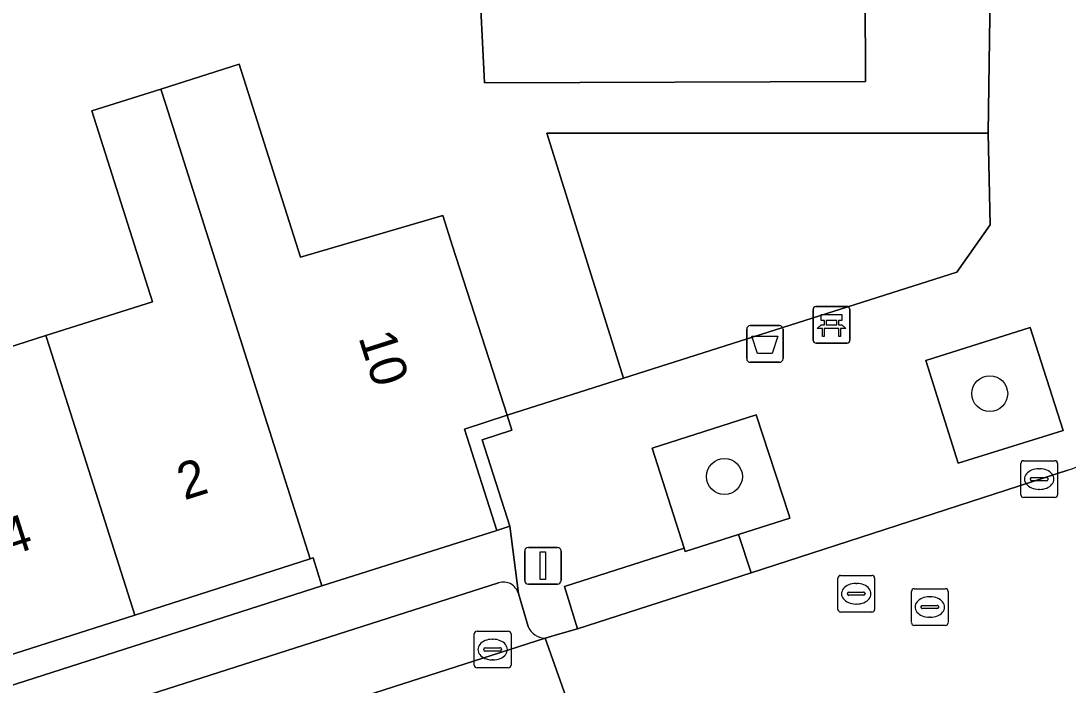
# Model space of a CAD drawing. Extents: x 159716 to 160783, y 383290 to 384031.
# Drawn here: x 160111.85 to 160140.37, y 383683.23 to 383701.33 of the extents above; entities that cross this region are included whole.
import ezdxf

# ---------------------------------------------------------------- set-up
doc = ezdxf.new("R2010")
doc.units = 0
for name, color, linetype in [('IMGEO_Afvalbak', 7, 'Continuous'), ('IMGEO_Bank', 7, 'Continuous'), ('IMGEO_Boom', 7, 'Continuous'), ('IMGEO_Erf', 7, 'Continuous'), ('IMGEO_Groenvoorziening', 7, 'Continuous'), ('IMGEO_Kolk', 7, 'Continuous'), ('IMGEO_Lichtmast', 7, 'Continuous'), ('IMGEO_Pand', 7, 'Continuous'), ('IMGEO_Pand_nummerreeks', 7, 'Continuous'), ('IMGEO_Parkeervlak_open', 7, 'Continuous'), ('IMGEO_Rijbaan_lokaal_open', 7, 'Continuous'), ('IMGEO_Rioolput', 7, 'Continuous'), ('IMGEO_Voetpad_open', 7, 'Continuous')]:
    doc.layers.add(name, color=color, linetype=linetype)

msp = doc.modelspace()

# ---------------------------------------------------------------- linework, layer by layer
at = {"layer": 'IMGEO_Afvalbak'}
for p, q in [((160131.716, 383693.027), (160132.506, 383693.027)), ((160132.506, 383693.027), (160131.716, 383693.027)), ((160131.616, 383692.127), (160131.616, 383692.927)), ((160131.616, 383692.927), (160131.616, 383692.127)), ((160132.606, 383692.927), (160132.606, 383692.127)), ((160132.606, 383692.127), (160132.606, 383692.927)), ((160132.506, 383692.027), (160131.716, 383692.027)), ((160131.716, 383692.027), (160132.506, 383692.027))]:
    msp.add_line(p, q, dxfattribs=at)
msp.add_lwpolyline([(160131.759, 383692.741), (160132.463, 383692.741), (160132.314, 383692.271), (160131.908, 383692.271), (160131.759, 383692.741)], dxfattribs=at)
for centre, start, end in [((160131.716, 383692.927), 90, 180), ((160131.716, 383692.927), 90, 180), ((160132.506, 383692.927), 0, 90), ((160132.506, 383692.927), 360, 90), ((160131.716, 383692.127), 180, 270), ((160131.716, 383692.127), 180, 270), ((160132.506, 383692.127), 270, 0), ((160132.506, 383692.127), 270, 0)]:
    msp.add_arc(centre, 0.1, start, end, dxfattribs=at)
at = {"layer": 'IMGEO_Bank'}
for p, q in [((160133.502, 383693.55), (160134.343, 383693.55)), ((160134.343, 383693.55), (160133.502, 383693.55)), ((160133.427, 383692.625), (160133.427, 383693.466)), ((160133.427, 383693.466), (160133.427, 383692.625)), ((160134.427, 383693.475), (160134.427, 383692.634)), ((160134.427, 383692.634), (160134.427, 383693.475)), ((160134.124, 383692.948), (160133.731, 383692.948)), ((160133.736, 383693.056), (160133.736, 383693.162)), ((160133.78, 383693.162), (160133.78, 383693.056)), ((160134.068, 383693.168), (160133.786, 383693.168)), ((160133.786, 383693.05), (160134.068, 383693.05)), ((160134.074, 383693.056), (160134.074, 383693.162)), ((160134.118, 383693.162), (160134.118, 383693.056)), ((160134.352, 383692.55), (160133.511, 383692.55)), ((160133.511, 383692.55), (160134.352, 383692.55))]:
    msp.add_line(p, q, dxfattribs=at)
for points in [[(160133.73, 383693.168), (160133.644, 383693.168), (160133.644, 383693.329), (160134.207, 383693.329), (160134.207, 383693.168), (160134.124, 383693.168)], [(160133.674, 383692.948), (160133.532, 383692.948), (160133.644, 383693.05), (160133.73, 383693.05)], [(160134.124, 383693.05), (160134.207, 383693.05), (160134.319, 383692.948), (160134.18, 383692.948)], [(160133.724, 383692.941), (160133.724, 383692.734), (160133.681, 383692.734), (160133.681, 383692.941)], [(160134.174, 383692.941), (160134.174, 383692.734), (160134.13, 383692.734), (160134.13, 383692.941)]]:
    msp.add_lwpolyline(points, dxfattribs=at)
for centre, radius, start, end in [((160133.505, 383693.472), 0.0779, 92.4484, 184.2845), ((160133.505, 383693.472), 0.0779, 92.4484, 184.2845), ((160134.349, 383693.472), 0.0779, 2.4484, 94.2845), ((160134.349, 383693.472), 0.0779, 2.4484, 94.2845), ((160133.674, 383692.941), 0.00671, 2.8957, 87.1043), ((160133.731, 383692.941), 0.00671, 92.8957, 177.1043), ((160133.729, 383693.161), 0.00671, 2.8957, 87.1043), ((160133.729, 383693.057), 0.00671, 272.8957, 357.1043), ((160133.786, 383693.161), 0.00671, 92.8957, 177.1043), ((160133.786, 383693.057), 0.00671, 182.8957, 267.1043), ((160134.068, 383693.161), 0.00671, 2.8957, 87.1043), ((160134.068, 383693.057), 0.00671, 272.8957, 357.1043), ((160134.125, 383693.161), 0.00671, 92.8957, 177.1043), ((160134.125, 383693.057), 0.00671, 182.8957, 267.1043), ((160134.123, 383692.941), 0.00671, 2.8957, 87.1043), ((160134.18, 383692.941), 0.00671, 92.8957, 177.1043), ((160133.505, 383692.628), 0.0779, 182.4484, 274.2845), ((160133.505, 383692.628), 0.0779, 182.4484, 274.2845), ((160134.349, 383692.628), 0.0779, 272.4484, 4.2845), ((160134.349, 383692.628), 0.0779, 272.4484, 4.2845)]:
    msp.add_arc(centre, radius, start, end, dxfattribs=at)
at = {"layer": 'IMGEO_Boom'}
for centre in [(160138.235, 383691.174), (160131.01, 383688.915)]:
    msp.add_circle(centre, 0.489, dxfattribs=at)
at = {"layer": 'IMGEO_Erf'}
for points in [[(160109.585, 383691.818), (160112.53, 383692.755), (160115.435, 383693.679), (160113.782, 383698.877), (160115.661, 383699.474), (160117.796, 383700.153), (160119.467, 383694.897), (160123.342, 383696.024), (160123.608, 383695.196), (160125.089, 383690.591), (160128.261, 383691.6), (160126.173, 383698.271), (160138.197, 383698.271), (160138.247, 383702.107)], [(160134.846, 383702.081), (160134.849, 383699.683), (160124.473, 383699.641), (160124.351, 383702.208)]]:
    msp.add_lwpolyline(points, dxfattribs=at)
for points in [[(160125.089, 383690.591), (160123.935, 383690.21), (160124.812, 383687.446), (160125.17, 383687.56), (160124.416, 383689.912), (160125.22, 383690.183)], [(160120.049, 383685.937), (160119.807, 383686.699), (160119.731, 383686.675), (160114.952, 383685.141), (160110.171, 383683.607), (160105.39, 383682.072), (160100.609, 383680.538), (160100.221, 383680.413), (160100.464, 383679.651)]]:
    msp.add_lwpolyline(points, close=True, dxfattribs=at)
at = {"layer": 'IMGEO_Groenvoorziening'}
for points in [[(160138.246, 383695.773), (160138.197, 383698.271), (160126.173, 383698.271), (160128.261, 383691.6), (160137.338, 383694.486)], [(160140.234, 383690.171), (160139.335, 383692.979), (160136.497, 383692.079), (160137.376, 383689.279)], [(160129.914, 383686.967), (160129.944, 383686.873), (160131.397, 383687.337), (160132.794, 383687.784), (160132.762, 383687.881), (160131.876, 383690.592), (160129.042, 383689.685)]]:
    msp.add_lwpolyline(points, close=True, dxfattribs=at)
at = {"layer": 'IMGEO_Kolk'}
for p, q in [((160139.082, 383688.419), (160139.082, 383689.271)), ((160139.157, 383689.345), (160140.009, 383689.345)), ((160140.083, 383689.271), (160140.083, 383688.419)), ((160139.57, 383689.125), (160139.595, 383689.125)), ((160139.341, 383688.839), (160139.341, 383688.851)), ((160139.779, 383688.802), (160139.381, 383688.802)), ((160139.384, 383688.888), (160139.782, 383688.888)), ((160139.825, 383688.851), (160139.825, 383688.839)), ((160139.593, 383688.565), (160139.568, 383688.565)), ((160140.009, 383688.345), (160139.157, 383688.345)), ((160124.272, 383684.701), (160125.124, 383684.701)), ((160124.197, 383683.775), (160124.197, 383684.627)), ((160124.685, 383684.481), (160124.71, 383684.481)), ((160125.198, 383684.627), (160125.198, 383683.775)), ((160124.456, 383684.195), (160124.456, 383684.207)), ((160124.894, 383684.158), (160124.496, 383684.158)), ((160124.499, 383684.244), (160124.897, 383684.244)), ((160124.94, 383684.207), (160124.94, 383684.195)), ((160124.708, 383683.921), (160124.683, 383683.921)), ((160125.124, 383683.701), (160124.272, 383683.701))]:
    msp.add_line(p, q, dxfattribs=at)
for points in [[(160139.082, 383688.419), (160139.082, 383689.271)], [(160139.157, 383689.345), (160140.009, 383689.345)], [(160140.083, 383689.271), (160140.083, 383688.419)], [(160140.009, 383688.345), (160139.157, 383688.345)], [(160124.272, 383684.701), (160125.124, 383684.701)], [(160124.197, 383683.775), (160124.197, 383684.627)], [(160125.198, 383684.627), (160125.198, 383683.775)], [(160125.124, 383683.701), (160124.272, 383683.701)]]:
    msp.add_lwpolyline(points, dxfattribs=at)
for centre, radius, start, end in [((160139.159, 383689.269), 0.0765, 91.552, 178.448), ((160139.159, 383689.269), 0.0765, 91.552, 178.448), ((160140.007, 383689.269), 0.0765, 1.552, 88.448), ((160140.007, 383689.269), 0.0765, 1.552, 88.448), ((160139.381, 383688.848), 0.0403, 85.8775, 175.7526), ((160139.378, 383688.838), 0.0366, 178.938, 274.7102), ((160139.782, 383688.845), 0.043, 264.8664, 352.4533), ((160139.786, 383688.85), 0.0386, 1.7309, 96.639), ((160139.159, 383688.421), 0.0765, 181.552, 268.448), ((160139.159, 383688.421), 0.0765, 181.552, 268.448), ((160140.007, 383688.421), 0.0765, 271.552, 358.448), ((160140.007, 383688.421), 0.0765, 271.552, 358.448), ((160124.274, 383684.625), 0.0765, 91.552, 178.448), ((160124.274, 383684.625), 0.0765, 91.552, 178.448), ((160125.122, 383684.625), 0.0765, 1.552, 88.448), ((160125.122, 383684.625), 0.0765, 1.552, 88.448), ((160124.496, 383684.204), 0.0403, 85.8775, 175.7526), ((160124.493, 383684.194), 0.0366, 178.938, 274.7102), ((160124.897, 383684.201), 0.043, 264.8664, 352.4533), ((160124.901, 383684.206), 0.0386, 1.7309, 96.639), ((160124.274, 383683.777), 0.0765, 181.552, 268.448), ((160124.274, 383683.777), 0.0765, 181.552, 268.448), ((160125.122, 383683.777), 0.0765, 271.552, 358.448), ((160125.122, 383683.777), 0.0765, 271.552, 358.448)]:
    msp.add_arc(centre, radius, start, end, dxfattribs=at)
for centre, major_axis, ratio, start_param, end_param in [((160139.569, 383688.845), (-0.387, 0.002), 0.722429, 4.712389, 7.853982), ((160139.594, 383688.845), (-0.39, 0.002), 0.717154, 1.570796, 4.712389), ((160124.684, 383684.201), (-0.387, 0.002), 0.722429, 4.712389, 7.853982), ((160124.709, 383684.201), (-0.39, 0.002), 0.717154, 1.570796, 4.712389)]:
    msp.add_ellipse(centre, major_axis=major_axis, ratio=ratio, start_param=start_param, end_param=end_param, dxfattribs=at)
at = {"layer": 'IMGEO_Lichtmast'}
for p, q in [((160125.67, 383686.984), (160126.46, 383686.984)), ((160126.46, 383686.984), (160125.67, 383686.984)), ((160125.57, 383686.084), (160125.57, 383686.884)), ((160125.57, 383686.884), (160125.57, 383686.084)), ((160126.56, 383686.884), (160126.56, 383686.084)), ((160126.56, 383686.084), (160126.56, 383686.884)), ((160126.46, 383685.984), (160125.67, 383685.984)), ((160125.67, 383685.984), (160126.46, 383685.984))]:
    msp.add_line(p, q, dxfattribs=at)
msp.add_lwpolyline([(160125.99, 383686.859), (160126.14, 383686.859), (160126.14, 383686.109), (160125.99, 383686.109), (160125.99, 383686.859)], dxfattribs=at)
for centre, start, end in [((160125.67, 383686.884), 90, 180), ((160125.67, 383686.884), 90, 180), ((160126.46, 383686.884), 0, 90), ((160126.46, 383686.884), 360, 90), ((160125.67, 383686.084), 180, 270), ((160125.67, 383686.084), 180, 270), ((160126.46, 383686.084), 270, 0), ((160126.46, 383686.084), 270, 0)]:
    msp.add_arc(centre, 0.1, start, end, dxfattribs=at)
at = {"layer": 'IMGEO_Pand'}
for points in [[(160138.221, 383705.895), (160129.395, 383705.861), (160129.058, 383705.86), (160129.073, 383702.227), (160124.351, 383702.208), (160124.473, 383699.641), (160134.849, 383699.683), (160134.846, 383702.081), (160138.247, 383702.107)], [(160123.342, 383696.024), (160119.467, 383694.897), (160117.796, 383700.153), (160115.661, 383699.474), (160115.794, 383699.057), (160119.731, 383686.675), (160119.807, 383686.699), (160120.049, 383685.937), (160124.812, 383687.446), (160123.935, 383690.21), (160125.089, 383690.591), (160123.608, 383695.196)], [(160115.794, 383699.057), (160115.661, 383699.474), (160113.782, 383698.877), (160115.435, 383693.679), (160112.53, 383692.755), (160112.627, 383692.45), (160114.952, 383685.141), (160119.731, 383686.675)], [(160112.627, 383692.45), (160112.53, 383692.755), (160109.585, 383691.818), (160108.018, 383696.744), (160106.18, 383696.159), (160106.252, 383695.932), (160110.171, 383683.607), (160114.952, 383685.141)]]:
    msp.add_lwpolyline(points, close=True, dxfattribs=at)
at = {"layer": 'IMGEO_Parkeervlak_open'}
for points in [[(160124.861, 383686.019), (160096.9, 383677.061)], [(160125.665, 383684.829), (160125.399, 383685.725)], [(160096.699, 383675.06), (160126.127, 383684.515)]]:
    msp.add_lwpolyline(points, dxfattribs=at)
for centre, radius, start, end in [((160124.99, 383685.615), 0.424, 15.0268, 107.6628), ((160126.117, 383684.998), 0.483, 200.4424, 271.1533)]:
    msp.add_arc(centre, radius, start, end, dxfattribs=at)
at = {"layer": 'IMGEO_Rijbaan_lokaal_open'}
for points in [[(160140.365, 383689.087), (160131.741, 383686.293), (160127.013, 383684.761), (160126.463, 383684.611), (160126.127, 383684.515), (160127.305, 383681.179), (160127.453, 383681.227), (160128.426, 383680.973)], [(160097.72, 383671.705), (160127.305, 383681.179), (160126.127, 383684.515), (160096.699, 383675.06), (160080.374, 383669.741)]]:
    msp.add_lwpolyline(points, dxfattribs=at)
msp.add_arc((160138.396, 383694.86), 6.1, 288.8278, 310.6866, dxfattribs=at)
at = {"layer": 'IMGEO_Rioolput'}
for p, q in [((160134.099, 383685.295), (160134.099, 383686.147)), ((160134.174, 383686.221), (160135.026, 383686.221)), ((160135.1, 383686.147), (160135.1, 383685.295)), ((160134.587, 383686.001), (160134.612, 383686.001)), ((160136.178, 383685.859), (160137.03, 383685.859)), ((160134.358, 383685.715), (160134.358, 383685.727)), ((160134.796, 383685.678), (160134.398, 383685.678)), ((160134.401, 383685.764), (160134.799, 383685.764)), ((160134.842, 383685.727), (160134.842, 383685.715)), ((160136.103, 383684.933), (160136.103, 383685.785)), ((160136.591, 383685.639), (160136.616, 383685.639)), ((160137.104, 383685.785), (160137.104, 383684.933)), ((160134.61, 383685.441), (160134.585, 383685.441)), ((160136.362, 383685.353), (160136.362, 383685.365)), ((160136.8, 383685.316), (160136.402, 383685.316)), ((160136.405, 383685.402), (160136.803, 383685.402)), ((160136.846, 383685.365), (160136.846, 383685.353)), ((160135.026, 383685.221), (160134.174, 383685.221)), ((160136.614, 383685.079), (160136.589, 383685.079)), ((160137.03, 383684.859), (160136.178, 383684.859))]:
    msp.add_line(p, q, dxfattribs=at)
for points in [[(160134.099, 383685.295), (160134.099, 383686.147)], [(160134.174, 383686.221), (160135.026, 383686.221)], [(160135.1, 383686.147), (160135.1, 383685.295)], [(160136.178, 383685.859), (160137.03, 383685.859)], [(160136.103, 383684.933), (160136.103, 383685.785)], [(160137.104, 383685.785), (160137.104, 383684.933)], [(160135.026, 383685.221), (160134.174, 383685.221)], [(160137.03, 383684.859), (160136.178, 383684.859)]]:
    msp.add_lwpolyline(points, dxfattribs=at)
for centre, radius, start, end in [((160134.176, 383686.145), 0.0765, 91.552, 178.448), ((160134.176, 383686.145), 0.0765, 91.552, 178.448), ((160135.024, 383686.145), 0.0765, 1.552, 88.448), ((160135.024, 383686.145), 0.0765, 1.552, 88.448), ((160136.18, 383685.783), 0.0765, 91.552, 178.448), ((160136.18, 383685.783), 0.0765, 91.552, 178.448), ((160137.028, 383685.783), 0.0765, 1.552, 88.448), ((160137.028, 383685.783), 0.0765, 1.552, 88.448), ((160134.398, 383685.724), 0.0403, 85.8775, 175.7526), ((160134.395, 383685.714), 0.0366, 178.938, 274.7102), ((160134.799, 383685.721), 0.043, 264.8664, 352.4533), ((160134.803, 383685.726), 0.0386, 1.7309, 96.639), ((160134.176, 383685.297), 0.0765, 181.552, 268.448), ((160134.176, 383685.297), 0.0765, 181.552, 268.448), ((160135.024, 383685.297), 0.0765, 271.552, 358.448), ((160135.024, 383685.297), 0.0765, 271.552, 358.448), ((160136.402, 383685.362), 0.0403, 85.8775, 175.7526), ((160136.399, 383685.352), 0.0366, 178.938, 274.7102), ((160136.803, 383685.359), 0.043, 264.8664, 352.4533), ((160136.807, 383685.364), 0.0386, 1.7309, 96.639), ((160136.18, 383684.935), 0.0765, 181.552, 268.448), ((160136.18, 383684.935), 0.0765, 181.552, 268.448), ((160137.028, 383684.935), 0.0765, 271.552, 358.448), ((160137.028, 383684.935), 0.0765, 271.552, 358.448)]:
    msp.add_arc(centre, radius, start, end, dxfattribs=at)
for centre, major_axis, ratio, start_param, end_param in [((160134.586, 383685.721), (-0.387, 0.002), 0.722429, 4.712389, 7.853982), ((160134.611, 383685.721), (-0.39, 0.002), 0.717154, 1.570796, 4.712389), ((160136.59, 383685.359), (-0.387, 0.002), 0.722429, 4.712389, 7.853982), ((160136.615, 383685.359), (-0.39, 0.002), 0.717154, 1.570796, 4.712389)]:
    msp.add_ellipse(centre, major_axis=major_axis, ratio=ratio, start_param=start_param, end_param=end_param, dxfattribs=at)
at = {"layer": 'IMGEO_Voetpad_open'}
for points in [[(160143.925, 383746.551), (160137.981, 383746.534), (160137.999, 383743.132), (160138.082, 383734.758), (160138.111, 383726.029), (160138.112, 383725.77), (160138.116, 383724.465), (160138.133, 383722.105), (160138.151, 383718.197), (160138.155, 383717.365), (160138.214, 383706.867), (160138.221, 383705.895), (160138.247, 383702.107), (160138.197, 383698.271), (160138.246, 383695.773), (160137.338, 383694.486), (160128.261, 383691.6), (160125.089, 383690.591), (160125.22, 383690.183), (160124.416, 383689.912), (160125.17, 383687.56), (160125.399, 383685.725), (160125.665, 383684.829)], [(160126.127, 383684.515), (160126.463, 383684.611), (160127.013, 383684.761), (160126.654, 383685.921), (160129.914, 383686.967), (160129.042, 383689.685), (160131.876, 383690.592), (160132.762, 383687.881), (160132.794, 383687.784), (160131.397, 383687.337), (160131.741, 383686.293), (160140.365, 383689.087)], [(160125.399, 383685.725), (160125.17, 383687.56), (160124.812, 383687.446), (160120.049, 383685.937), (160100.464, 383679.651), (160095.984, 383678.221), (160078.278, 383672.594)], [(160096.9, 383677.061), (160124.861, 383686.019)]]:
    msp.add_lwpolyline(points, dxfattribs=at)
for points in [[(160139.335, 383692.979), (160140.234, 383690.171), (160137.376, 383689.279), (160136.497, 383692.079)], [(160131.741, 383686.293), (160131.397, 383687.337), (160129.944, 383686.873), (160129.914, 383686.967), (160126.654, 383685.921), (160127.013, 383684.761)]]:
    msp.add_lwpolyline(points, close=True, dxfattribs=at)
for centre, radius, start, end in [((160138.396, 383694.86), 6.1, 288.8278, 310.6866), ((160124.99, 383685.615), 0.424, 15.0268, 107.6628), ((160126.117, 383684.998), 0.483, 200.4424, 271.1533)]:
    msp.add_arc(centre, radius, start, end, dxfattribs=at)

# ---------------------------------------------------------------- texts
at = {"layer": 'IMGEO_Pand_nummerreeks'}
for s, rotation, p in [('10', 287.6469, (160121.037, 383692.71)), ('2', 17.6414, (160116.301, 383688.263)), ('4', 17.6414, (160111.519, 383686.742))]:
    msp.add_text(s, height=1, rotation=rotation, dxfattribs=at).set_placement(p)

doc.saveas('drawing.dxf')
